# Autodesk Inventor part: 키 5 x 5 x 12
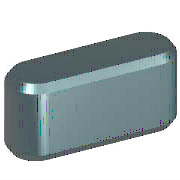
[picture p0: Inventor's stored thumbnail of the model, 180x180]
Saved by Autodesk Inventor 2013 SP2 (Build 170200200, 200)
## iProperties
IsCustomPart: 1
Created: 2012-02
Part Number: 키 5 x 5 x 12
Material: 강철, 연강
Description: 키 및 해당 키홈
Document SubType Name: Modeling
Standard: KS B 1311
Designer: mduedu
Standards Organization: KS
Language: ko-KR
Size Designation: 5 x 5 x 12
Categories: <MemberInstance><Categories><Category DisplayName="샤프트 부품" InternalName="7f7aeb1f-a693-4053-b835-cee3144e0d98" Mnemonic="SHFT"><Category DisplayName="키" Interna
Density: 7.86 g/cm^3
Mass: 2.11085 g
Surface Area: 2.43471 cm^2
Volume: 0.268556 cm^3
Author: mduedu
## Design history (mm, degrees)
workplane "Work Plane1"
workplane "Work Plane2"
sketch "스케치1"
  geometry: L1 (2.5, 2.5)-(9.5, 2.5); L2 (9.5, -2.5)-(2.5, -2.5); L3 (0, 9.4)-(0, -7.4) reference; L4 (-5, 0)-(30, 0) reference; L5 (12, 0)-(12, 7); A1 r 2.5 centre (2.5, 0) between (2.5, 2.5) and (2.5, -2.5); A2 r 2.5 centre (9.5, 0) between (9.5, -2.5) and (9.5, 2.5)
  constraints: 6 end point, 5 point on circle, 4 tangent, 3 point on line, 2 centre point, 1 horizontal, 1 parallel, 1 perpendicular
  dimensions: "d0" = 2.5 radius of A1 (= 0.5 x PB); "d13" = 2.5 radius of A2 (= 0.5 x PB); "d14" = 12 distance between parallel lines of L5 L3 (= NLG)
extrude "본체1" new body sketch "스케치1" taper "d3" = 0 deg; stored distance "d4" = 10
workplane "Work Plane3"
body "Solid1"
chamfer "모따기1" distance "d8" = 0.4 (= PHH); stored, may be unused: second distance "d9" = 0.4 (= PHH), angle "d15" = 45 deg
other parameters: "d1" = -3 (= -PNT), "d2" = 2 (= PH - PNT), "NLG" = 12 [user parameter; used in 3 equation terms], "PB" = 5 [user parameter; used in 2 equation terms], "PNT" = 3 [user parameter; used in 2 equation terms], "PH" = 5 [user parameter; used in 1 equation term], "PHH" = 0.4 [user parameter; used in 2 equation terms], "d10" = 0, "d16" = 0, "d17" = 0, "d18" = 0, "WDMIN" = 12 [user parameter], "PLB2" = 12 (= NLG) [user parameter], "WDMAX" = 17 [user parameter], "PLB1" = 12 (= NLG) [user parameter], "RR" = 0.16 [user parameter], "PUEB" = 2.3 [user parameter]
